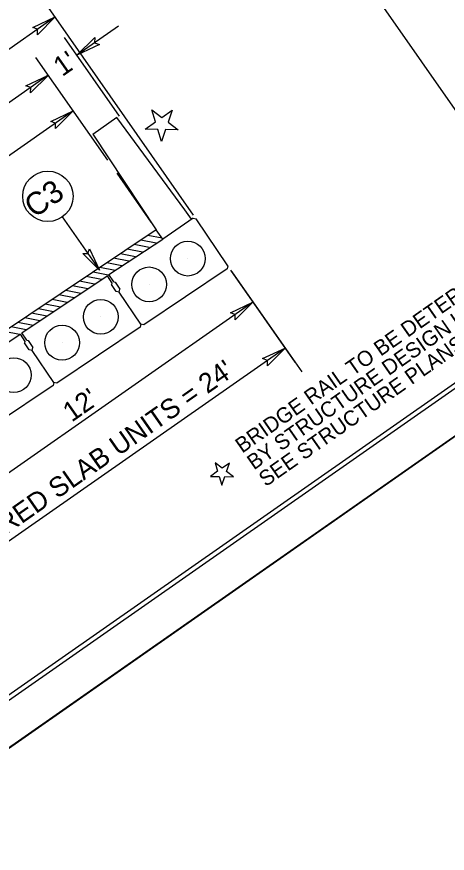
# Model space of a CAD drawing. Extents: x 1033697 to 1037131, y 657437 to 660507.
# Drawn here: x 1036096.5 to 1036343.3, y 658699.5 to 659178.7 of the extents above; entities that cross this region are included whole.
import ezdxf

# ---------------------------------------------------------------- set-up
doc = ezdxf.new("R2010")
doc.units = 0
for name, color, linetype in [('Default', 7, 'Continuous'), ('Prop RDY Traffic Signal CELL', 7, 'Continuous'), ('Sheet Cutting Line CELL', 7, 'Continuous'), ('Sheet Data Field CELL', 7, 'Continuous'), ('Sheet Plot Border Inside CELL', 7, 'Continuous'), ('Sheet Plot Border Outside CELL', 7, 'Continuous'), ('Sheet Typical CELL', 7, 'Continuous'), ('Typical ID Circle CELL', 7, 'Continuous'), ('Typical Terminator CELL', 7, 'Continuous'), ('Typical Text ID Circle CELL', 7, 'Continuous')]:
    doc.layers.add(name, color=color, linetype=linetype)

msp = doc.modelspace()

# ---------------------------------------------------------------- linework, layer by layer
at = {"layer": 'Default'}
for p, q in [((1036421.21, 659020.46), (1036273.04, 659232.54)), ((1036197.89, 659065.08), (1036110.57, 659190.01)), ((1036118.55, 659178.6), (1035725.09, 658903.6)), ((1036154.87, 659173.39), (1036131.01, 659156.71)), ((1036155.42, 659121.78), (1036123.88, 659166.92)), ((1036148.69, 659096.48), (1036107.47, 659155.45)), ((1036114.55, 659145.31), (1035757.31, 658895.62)), ((1036128.88, 659124.82), (1035950.45, 659000.11)), ((1036140.19, 659111.54), (1036153.9, 659121.12)), ((1036192.88, 659068.16), (1036153.85, 659121.09)), ((1036140.19, 659111.54), (1036176.49, 659056.7)), ((1036153.88, 659089.04), (1036173.4, 659061.13)), ((1036196.7, 659062.69), (1036192.88, 659068.16)), ((1036197.61, 659063.33), (1036180.31, 659051.24)), ((1036197.62, 659063.33), (1036199.36, 659062.99)), ((1036217.44, 659035.97), (1036199.36, 659062.99)), ((1036176.49, 659056.7), (1035814.26, 658814.22)), ((1036180.31, 659051.24), (1036176.49, 659056.7)), ((1036149.3, 659030.98), (1036180.31, 659051.24)), ((1036176.36, 659049.1), (1036167.69, 659050.82)), ((1036179.92, 659051.79), (1036171.61, 659053.44)), ((1036168.53, 659043.85), (1036159.86, 659045.57)), ((1036172.45, 659046.48), (1036163.77, 659048.19)), ((1036160.7, 659038.61), (1036152.02, 659040.33)), ((1036164.61, 659041.23), (1036155.94, 659042.95)), ((1036194.54, 659040.2), (1036194.54, 659040.2)), ((1036156.78, 659035.99), (1036148.1, 659037.71)), ((1036217.44, 659035.97), (1036217.1, 659034.23)), ((1036148.94, 659030.74), (1036140.27, 659032.46)), ((1036152.86, 659033.37), (1036144.19, 659035.08)), ((1036148.78, 659030.63), (1036148.78, 659030.63)), ((1036152.09, 659026.82), (1036149.3, 659030.98)), ((1036217.1, 659034.23), (1036169.3, 659002.23)), ((1036219.05, 659033.63), (1036255.93, 658980.86)), ((1036219.75, 659032.62), (1036259.87, 658975.23)), ((1036219.75, 659032.62), (1036248.41, 658991.62)), ((1036099.42, 658997.59), (1036148.26, 659030.29)), ((1036141.11, 659025.5), (1036132.44, 659027.22)), ((1036145.03, 659028.12), (1036136.35, 659029.84)), ((1036148.26, 659030.29), (1036151.05, 659026.12)), ((1036151.05, 659026.12), (1036150.87, 659025.26)), ((1036152.09, 659026.82), (1036152.95, 659026.65)), ((1036152.95, 659026.65), (1036155.62, 659022.67)), ((1036133.27, 659020.25), (1036124.6, 659021.97)), ((1036137.19, 659022.88), (1036128.52, 659024.59)), ((1036153.54, 659021.28), (1036150.87, 659025.26)), ((1036155.27, 659020.93), (1036153.54, 659021.28)), ((1036155.27, 659020.93), (1036155.62, 659022.67)), ((1036167.56, 659002.58), (1036155.27, 659020.93)), ((1036167.56, 659002.58), (1036155.27, 659020.93)), ((1036172.38, 659025.36), (1036172.38, 659025.36)), ((1036125.44, 659015.01), (1036116.77, 659016.73)), ((1036129.36, 659017.63), (1036120.68, 659019.35)), ((1036231.89, 659015.25), (1036035.71, 658878.13)), ((1036117.6, 659009.76), (1036108.93, 659011.48)), ((1036121.52, 659012.39), (1036112.85, 659014.1)), ((1036113.69, 659007.14), (1036105.01, 659008.86)), ((1036144.66, 659006.81), (1036144.66, 659006.81)), ((1036105.85, 659001.9), (1036097.18, 659003.61)), ((1036109.77, 659004.52), (1036101.1, 659006.24)), ((1036167.56, 659002.58), (1036167.22, 659000.84)), ((1036169.3, 659002.23), (1036167.56, 659002.58)), ((1036098.02, 658996.65), (1036089.34, 658998.37)), ((1036101.94, 658999.27), (1036093.26, 659000.99)), ((1036098.9, 658997.24), (1036098.9, 658997.24)), ((1036098.92, 658997.25), (1036098.92, 658997.25)), ((1036102.21, 658993.43), (1036099.42, 658997.59)), ((1036167.22, 659000.84), (1036119.42, 658968.84)), ((1036049.54, 658964.2), (1036098.38, 658996.89)), ((1036098.38, 658996.89), (1036101.16, 658992.73)), ((1036101.16, 658992.73), (1036100.99, 658991.86)), ((1036102.21, 658993.43), (1036103.07, 658993.26)), ((1036103.07, 658993.26), (1036105.74, 658989.28)), ((1036250.3, 658988.92), (1035856.74, 658713.85)), ((1036103.65, 658987.88), (1036100.99, 658991.86)), ((1036105.39, 658987.54), (1036103.65, 658987.88)), ((1036105.39, 658987.54), (1036105.74, 658989.28)), ((1036117.68, 658969.18), (1036105.39, 658987.54)), ((1036117.7, 658969.2), (1036105.41, 658987.55)), ((1036122.49, 658991.97), (1036122.49, 658991.97)), ((1036117.68, 658969.18), (1036117.34, 658967.44)), ((1036119.42, 658968.84), (1036117.68, 658969.18)), ((1036117.34, 658967.44), (1036069.54, 658935.45))]:
    msp.add_line(p, q, dxfattribs=at)
for centre in [(1036194.55, 659040.2), (1036172.38, 659025.36), (1036144.66, 659006.81), (1036122.5, 658991.97), (1036094.78, 658973.41)]:
    msp.add_circle(centre, 10, dxfattribs=at)
at = {"layer": 'Prop RDY Traffic Signal CELL'}
for points in [[(1036179.66, 659121.04), (1036185.61, 659125.19), (1036183.24, 659118.34), (1036189.04, 659113.96), (1036181.77, 659114.09), (1036179.4, 659107.23), (1036177.28, 659114.17), (1036170.02, 659114.31), (1036175.98, 659118.46), (1036173.86, 659125.42), (1036179.66, 659121.04)], [(1036211.66, 658918.29), (1036207.5, 658915.38), (1036212.58, 658915.29), (1036214.06, 658910.42), (1036215.72, 658915.24), (1036220.81, 658915.14), (1036216.75, 658918.21), (1036218.41, 658923.01), (1036214.24, 658920.1), (1036210.18, 658923.16), (1036211.66, 658918.29)]]:
    msp.add_lwpolyline(points, dxfattribs=at)
at = {"layer": 'Sheet Cutting Line CELL'}
for p, q in [((1035661.22, 658458.77), (1037041.5, 659423.5)), ((1037041.5, 659423.5), (1035661.22, 658458.77))]:
    msp.add_line(p, q, dxfattribs=at)
at = {"layer": 'Sheet Plot Border Inside CELL'}
msp.add_lwpolyline([(1036420.5, 660304.13), (1035054.57, 659349.42), (1035659.01, 658484.62), (1037024.95, 659439.32)], close=True, dxfattribs=at)
at = {"layer": 'Sheet Plot Border Outside CELL'}
msp.add_lwpolyline([(1036411.33, 660325.1), (1035031.05, 659360.38), (1035661.22, 658458.77), (1037041.5, 659423.5)], close=True, dxfattribs=at)
at = {"layer": 'Sheet Typical CELL'}
msp.add_lwpolyline([(1036411.72, 660294.87), (1035182.26, 659435.56), (1035783.78, 658574.94), (1037013.24, 659434.25)], close=True, dxfattribs=at)
at = {"layer": 'Typical ID Circle CELL'}
msp.add_line((1036122.57, 659064.03), (1036143.92, 659033.46), dxfattribs=at)
msp.add_circle((1036114.31, 659075.85), 14.43, dxfattribs=at)
at = {"layer": 'Typical Terminator CELL'}
for points in [[(1036105.63, 659172.54), (1036118.55, 659178.6), (1036108.39, 659168.46), (1036108.43, 659171.54)], [(1036143.92, 659162.77), (1036131.01, 659156.71), (1036141.17, 659166.85), (1036141.13, 659163.78)], [(1036101.69, 659139.17), (1036114.6, 659145.24), (1036104.45, 659135.09), (1036104.49, 659138.17)], [(1036115.96, 659118.75), (1036128.88, 659124.82), (1036118.72, 659114.67), (1036118.76, 659117.75)], [(1036138.15, 659045.73), (1036143.92, 659033.46), (1036134.28, 659043.11), (1036137.2, 659043.08)], [(1036218.98, 659009.18), (1036231.89, 659015.25), (1036221.73, 659005.11), (1036221.77, 659008.18)], [(1036237.38, 658982.85), (1036250.3, 658988.92), (1036240.14, 658978.77), (1036240.18, 658981.85)]]:
    msp.add_lwpolyline(points, close=True, dxfattribs=at)

# ---------------------------------------------------------------- texts
at = {"layer": 'Default'}
for s, p in [("1'", (1036122.57, 659144.15)), ("8 PRESTRESSED CONCRETE CORED SLAB UNITS = 24'", (1035893.65, 658744.27)), ("12'", (1036127.99, 658946.17))]:
    msp.add_text(s, height=11.25, rotation=34.9511, dxfattribs=at).set_placement(p)
at = {"layer": 'Sheet Data Field CELL'}
for s, p in [('BRIDGE RAIL TO BE DETERMINED', (1036225.71, 658928.41)), ('BY STRUCTURE DESIGN UNIT,', (1036232.44, 658918.78)), ('SEE STRUCTURE PLANS.', (1036239.17, 658909.15))]:
    msp.add_text(s, height=8.75, rotation=34.9512, dxfattribs=at).set_placement(p)
at = {"layer": 'Typical Text ID Circle CELL'}
msp.add_text('C3', height=12.912, rotation=34.9389, dxfattribs=at).set_placement((1036106.64, 659063.06))

doc.saveas('drawing.dxf')
